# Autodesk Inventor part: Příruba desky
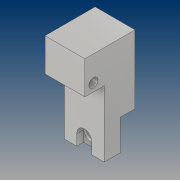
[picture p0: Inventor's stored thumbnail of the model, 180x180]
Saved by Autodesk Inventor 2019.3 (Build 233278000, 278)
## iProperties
Created: 2019-01
Part Number: Příruba desky
Material: Hliník 6061-AHC
Document SubType Name: Modeling
Designer: B-hon
Density: 2.7 g/cm^3
Appearance: Hliník – tmavý
Author: B-hon
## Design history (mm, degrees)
sketch "Náčrt1"
  geometry: L1 (-32.5, 40)-(32.5, 40); L2 (32.5, 40)-(32.5, -40); L3 (32.5, -40)-(-32.5, -40); L4 (-32.5, -40)-(-32.5, 40); L5 (-32.5, 40)-(32.5, -40); L6 (32.5, 40)-(-32.5, -40); 1 further point
  constraints: 12 end point, 2 midpoint, 2 parallel, 1 horizontal, 1 perpendicular
  dimensions: "d0" = 65 distance of L2.end L3.end; "d1" = 80 distance of L1.end L2.end
extrude "Vysunutí1" new body sketch "Náčrt1" distance "d2" = 26; taper "d3" = 0 deg
sketch "Náčrt2"
  geometry: L1 (-44.381, 28)-(47.748, 28); L2 (47.748, 28)-(47.748, 22); L3 (47.748, 22)-(-44.381, 22); L4 (-44.381, 22)-(-44.381, 28); L5 (-44.381, 28)-(47.748, 22); L6 (47.748, 28)-(-44.381, 22); L7 (-32.5, -40)-(32.5, -40) reference; L8 (-38.512, 18)-(43.239, 18); L9 (43.239, 18)-(43.239, -45.522); L10 (43.239, -45.522)-(-38.512, -45.522); L11 (-38.512, -45.522)-(-38.512, 18); L12 (-32.5, 40)-(-32.5, -40) reference; 2 further points
  constraints: 20 end point, 4 parallel, 2 horizontal, 2 midpoint, 2 perpendicular
  dimensions: "d4" = 6 distance of L1.end L2.end; "d5" = 65 distance from line of L7 point (1.683, 25); "d6" = 7 distance from line of L8 point (1.683, 25)
extrude "Vysunutí2" cut sketch "Náčrt2" distance "d10" = 14; taper "d11" = 0 deg
sketch "Náčrt3"
  geometry: L1 (-39.607, 44.84)-(-17.5, 44.84); L2 (-17.5, 44.84)-(-17.5, 11.926); L3 (-17.5, 11.926)-(-39.607, 11.926); L4 (-39.607, 11.926)-(-39.607, 44.84); L5 (17.5, 44.045)-(36.686, 44.045); L6 (36.686, 44.045)-(36.686, 9.931); L7 (36.686, 9.931)-(17.5, 9.931); L8 (17.5, 9.931)-(17.5, 44.045); L9 (-32.5, 40)-(-32.5, 18) reference; 1 further point
  constraints: 16 end point, 4 parallel, 2 horizontal, 2 perpendicular
  dimensions: "d12" = 35 distance between parallel lines of L8 L2; "d13" = 15 distance between parallel lines of L9 L2
extrude "Vysunutí3" cut sketch "Náčrt3" distance "d14" = 14; taper "d15" = 0 deg
sketch "Náčrt4"
  geometry: L1 (26, -58)-(14, -58) reference; L2 (0, 0)-(0, 22) reference; 2 further points
  dimensions: "d16" = 65 distance from line of L1 point (4.5, 7); "d17" = 4.5 distance from line of L2 point (4.5, 7)
hole "Díra1" sketch "Náčrt4" at (4.5, 7) diameter "d18" = 8; stored, may be unused: countersink angle "d22" = 90 deg, drill point angle "d24" = 118 deg; dims "d19" = 6, "d20" = 11, "d21" = 6.8, "d23" = 8
node "Upravit přímo1"
sketch "Náčrt6"
  geometry: L1 (32.5, -40)-(-32.5, -40) reference; C1 r 6.5 at (0, -30); 1 further point
  constraints: 1 centre point
  dimensions: "d39" = 13 diameter of C1; "d40" = 10 distance from line of L1 C1.centre
extrude "Vysunutí4" cut sketch "Náčrt6" distance "d41" = 8; taper "d42" = 0 deg
sketch "Náčrt7"
  geometry: L1 (-6.5, -61.308)-(6.5, -61.308); L2 (6.5, -61.308)-(6.5, -30.361); L3 (6.5, -30.361)-(-6.5, -30.361); L4 (-6.5, -30.361)-(-6.5, -61.308); L5 (-6.5, -61.308)-(6.5, -30.361); L6 (6.5, -61.308)-(-6.5, -30.361); 2 further points
  constraints: 12 end point, 2 midpoint, 2 parallel, 1 horizontal, 1 perpendicular
  dimensions: "d43" = 13 distance of L3.end L2.end
extrude "Vysunutí5" cut sketch "Náčrt7" distance "d44" = 6; taper "d45" = 0 deg
node "Upravit přímo2"
sketch "Náčrt10"
  geometry: L1 (-48.128, 53.565)-(-17.5, 53.565); L2 (-17.5, 53.565)-(-17.5, -46.218); L3 (-17.5, -46.218)-(-48.128, -46.218); L4 (-48.128, -46.218)-(-48.128, 53.565); L5 (17.5, 54.3)-(38.723, 54.3); L6 (38.723, 54.3)-(38.723, -45.483); L7 (38.723, -45.483)-(17.5, -45.483); L8 (17.5, -45.483)-(17.5, 54.3); L9 (-17.5, 45)-(-17.5, 18) reference; L10 (17.5, 18)-(17.5, 45) reference; 1 further point
  constraints: 16 end point, 4 parallel, 2 horizontal, 2 perpendicular
  dimensions: "d67" = 0 distance between parallel lines of L9 L2; "d68" = 0 distance between parallel lines of L8 L10
extrude "Vysunutí6" cut sketch "Náčrt10" distance "d69" = 15; taper "d70" = 0 deg
node "Upravit přímo4"
node "Upravit přímo6"
sketch "Náčrt14"
  geometry: L1 (0, 87)-(35, 87); L2 (35, 87)-(35, 27); L3 (35, 27)-(0, 27); L4 (0, 27)-(0, 87); L5 (0, 87)-(0, 0) reference; L6 (35, 87)-(0, 87) reference; 1 further point
  constraints: 8 end point, 2 parallel, 1 horizontal, 1 perpendicular
  dimensions: "d107" = 35 distance of L2.end L3.end; "d108" = 0 distance between parallel lines of L5 L4; "d109" = 60 distance between parallel lines of L1 L3; "d110" = 60 distance between parallel lines of L3 L6
extrude "Vysunutí8" join sketch "Náčrt14" distance "d111" = 13; taper "d112" = 0 deg
sketch "Náčrt15"
  geometry: L1 (0, 27)-(35, 27) reference; L2 (0, 87)-(0, 27) reference; 4 further points
  constraints: 1 horizontal alignment
  dimensions: "d113" = 21 distance of point (28, 34) point (7, 34); "d114" = 7 distance from line of L1 point (7, 34); "d115" = 7 distance from line of L2 point (7, 34); "d116" = 10.5 horizontal distance of point (28, 34) point (17.5, 79); "d117" = 52 distance from line of L1 point (17.5, 79)
hole "Díra7" sketch "Náčrt15" at (7, 34), (28, 34), (17.5, 79) diameter "d118" = 4.134; stored, may be unused: countersink angle "d122" = 90 deg, drill point angle "d124" = 118 deg; dims "d119" = 15, "d120" = 4, "d121" = 2, "d123" = 20
chamfer "Zkosení1" distance "d125" = 0.5; stored, may be unused: second distance "d126" = 2, angle "d127" = 45 deg
node "Těleso1"
feature "Posunout1" dims "d27" = 5
feature "Posunout2" dims "d48" = 3
feature "Posunout4" dims "d76" = 2
feature "Posunout6" dims "d100" = 2
other parameters: "d25" = 0, "d26" = 0, "d46" = 0, "d47" = 0, "d74" = 0, "d75" = 0, "d98" = 0, "d99" = 0
